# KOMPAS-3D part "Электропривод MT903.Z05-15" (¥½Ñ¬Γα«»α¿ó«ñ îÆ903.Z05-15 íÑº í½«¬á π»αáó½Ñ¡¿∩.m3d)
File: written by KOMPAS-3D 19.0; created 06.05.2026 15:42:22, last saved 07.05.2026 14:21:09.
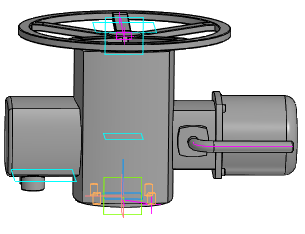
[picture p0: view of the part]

Document properties: Автор: Энергия; Полное имя файла: Z:\3.Личные\kachalov\3d для проектировщиков\2.2 Тип 47GVA, 47GVA.Z\Привод\Электропривод МТ903.Z05-15 без блока управления.m3d

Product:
- Part/product: Электропривод MT903.Z05-15
    Масса: 49.8062
  - Body: Тело 1
      Масса: 49.4272
  - Body: Тело 4
      Масса: 49.4272

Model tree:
1. Эскиз:1
2. Элемент выдавливания:1
     Расстояние 1 = 202
3. Эскиз:2
4. Элемент выдавливания:2
     Расстояние 1 = 120
5. Эскиз:3  (with: Элемент выдавливания:2)
6. Элемент выдавливания:3
     Расстояние 1 = 8
7. Эскиз:4  (with: Элемент выдавливания:3)
8. Элемент выдавливания:4
     Расстояние 1 = 100
9. Скругление:1  (with: Элемент выдавливания:4)
     Радиус = 15
10. Эскиз:5
11. Элемент выдавливания:5
     Расстояние 1 = 99
12. Эскиз:6  (with: Элемент выдавливания:5)
13. Элемент выдавливания:6
     Расстояние 1 = 8
14. Эскиз:7  (with: Элемент выдавливания:6)
15. Элемент выдавливания:7
     Расстояние 1 = 40
16. Скругление:2  (with: Элемент выдавливания:7)
     Радиус = 10
17. Эскиз:8
18. Элемент выдавливания:8
     Расстояние 1 = 154
19. Скругление:3  (with: Элемент выдавливания:8)
     Радиус = 5
20. Касательная плоскость:1  (with: Элемент выдавливания:8)
21. Эскиз:10
22. Элемент выдавливания:9
     Расстояние 1 = 5
23. Эскиз:11  (with: Элемент выдавливания:9)
24. Отверстие:1  (with: Элемент выдавливания:9)  (labels: M10)
     Глубина выреза = 20; Диаметр отверстия = 8.3762; Угол конуса дна = 118; Расстояние 1 = -36.0624; Расстояние 2 = -36.0624
25. M10  (with: Элемент выдавливания:9)  (labels: cil0_24705-2004 coarse)
     Длина резьбы = 15; Шаг резьбы = 1.5; Номинальный диаметр резьбы = 10
26. Массив по концентрической сетке:1  (with: Отверстие:1, Эскиз:11)  (labels: M10)  (2 pattern instances)
27. Отверстие:1  (with: Эскиз:11)  (labels: M10)
28. Отверстие:1  (with: Эскиз:11)  (labels: M10)
29. Эскиз:12  (with: Элемент выдавливания:9)
30. Элемент выдавливания:10
     Расстояние 1 = 3
31. Эскиз:13  (with: Элемент выдавливания:10)
32. Элемент выдавливания:11
     Расстояние 2 = 50
33. Эскиз:14
34. Элемент выдавливания:14  (with: Элемент выдавливания:8)
     Расстояние 1 = 15; Расстояние 2 = 10
35. Эскиз:15  (with: Элемент выдавливания:1)
36. Элемент выдавливания:15
     Расстояние 1 = 5
37. Эскиз:16  (with: Элемент выдавливания:15)
38. Смещенная плоскость:1  (with: Элемент выдавливания:15)
     Расстояние = 18
39. Эскиз:17  (with: Элемент выдавливания:15)
40. Элемент выдавливания:16
     Расстояние 1 = 10
41. Элемент выдавливания:17
     Расстояние 1 = 10
42. Эскиз:20  (with: Элемент выдавливания:16, Элемент выдавливания:17)
43. Перпендикулярная плоскость:1
44. Эскиз:21
45. Элемент по траектории:1
46. Скругление:4  (with: Элемент выдавливания:17, Элемент по траектории:1, Элемент выдавливания:16)
     Радиус = 1
47. Массив по концентрической сетке:2  (with: Элемент по траектории:1, Эскиз:21, Скругление:4, Элемент выдавливания:15)  (5 pattern instances)
     Шаг 2 = 360
48. Скругление:5  (with: Элемент выдавливания:14, Элемент выдавливания:7, Элемент выдавливания:4)
     Радиус = 1
49. Эскиз:22  (with: Элемент выдавливания:3, Скругление:5)
50. Элемент выдавливания:18
     Расстояние 1 = 5
51. Скругление:6  (with: Элемент выдавливания:18)
     Радиус = 1
52. Массив по концентрической сетке:3  (with: Элемент выдавливания:18, Эскиз:22, Скругление:6, Элемент выдавливания:4)  (4 pattern instances)
     Шаг 2 = 360
53. Эскиз:23  (with: Элемент выдавливания:6, Скругление:5)
54. Элемент выдавливания:19
     Расстояние 1 = 5
55. Скругление:7  (with: Элемент выдавливания:19)
     Радиус = 1
56. Массив по концентрической сетке:4  (with: Элемент выдавливания:19, Эскиз:23, Скругление:7, Элемент выдавливания:7)  (4 pattern instances)
     Шаг 2 = 360
57. Эскиз:24
58. Элемент выдавливания:20
     Расстояние 1 = 40
59. Смещенная плоскость:2
60. Эскиз:25  (with: Элемент выдавливания:20)
61. Эскиз:26  (with: Элемент выдавливания:20)
62. Элемент по траектории:2
63. Фаска:1  (with: Элемент по траектории:2)
     Угол = 45; Длина 1 = 2; Длина 2 = 2
64. Эскиз:27  (with: Элемент выдавливания:7)
65. Элемент выдавливания:21
     Расстояние 1 = 3
66. Эскиз:28  (with: Элемент выдавливания:21)
67. Элемент выдавливания:22
     Расстояние 2 = 1

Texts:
  Точка начала. Х
  Точка начала. Y
  Точка начала. Z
